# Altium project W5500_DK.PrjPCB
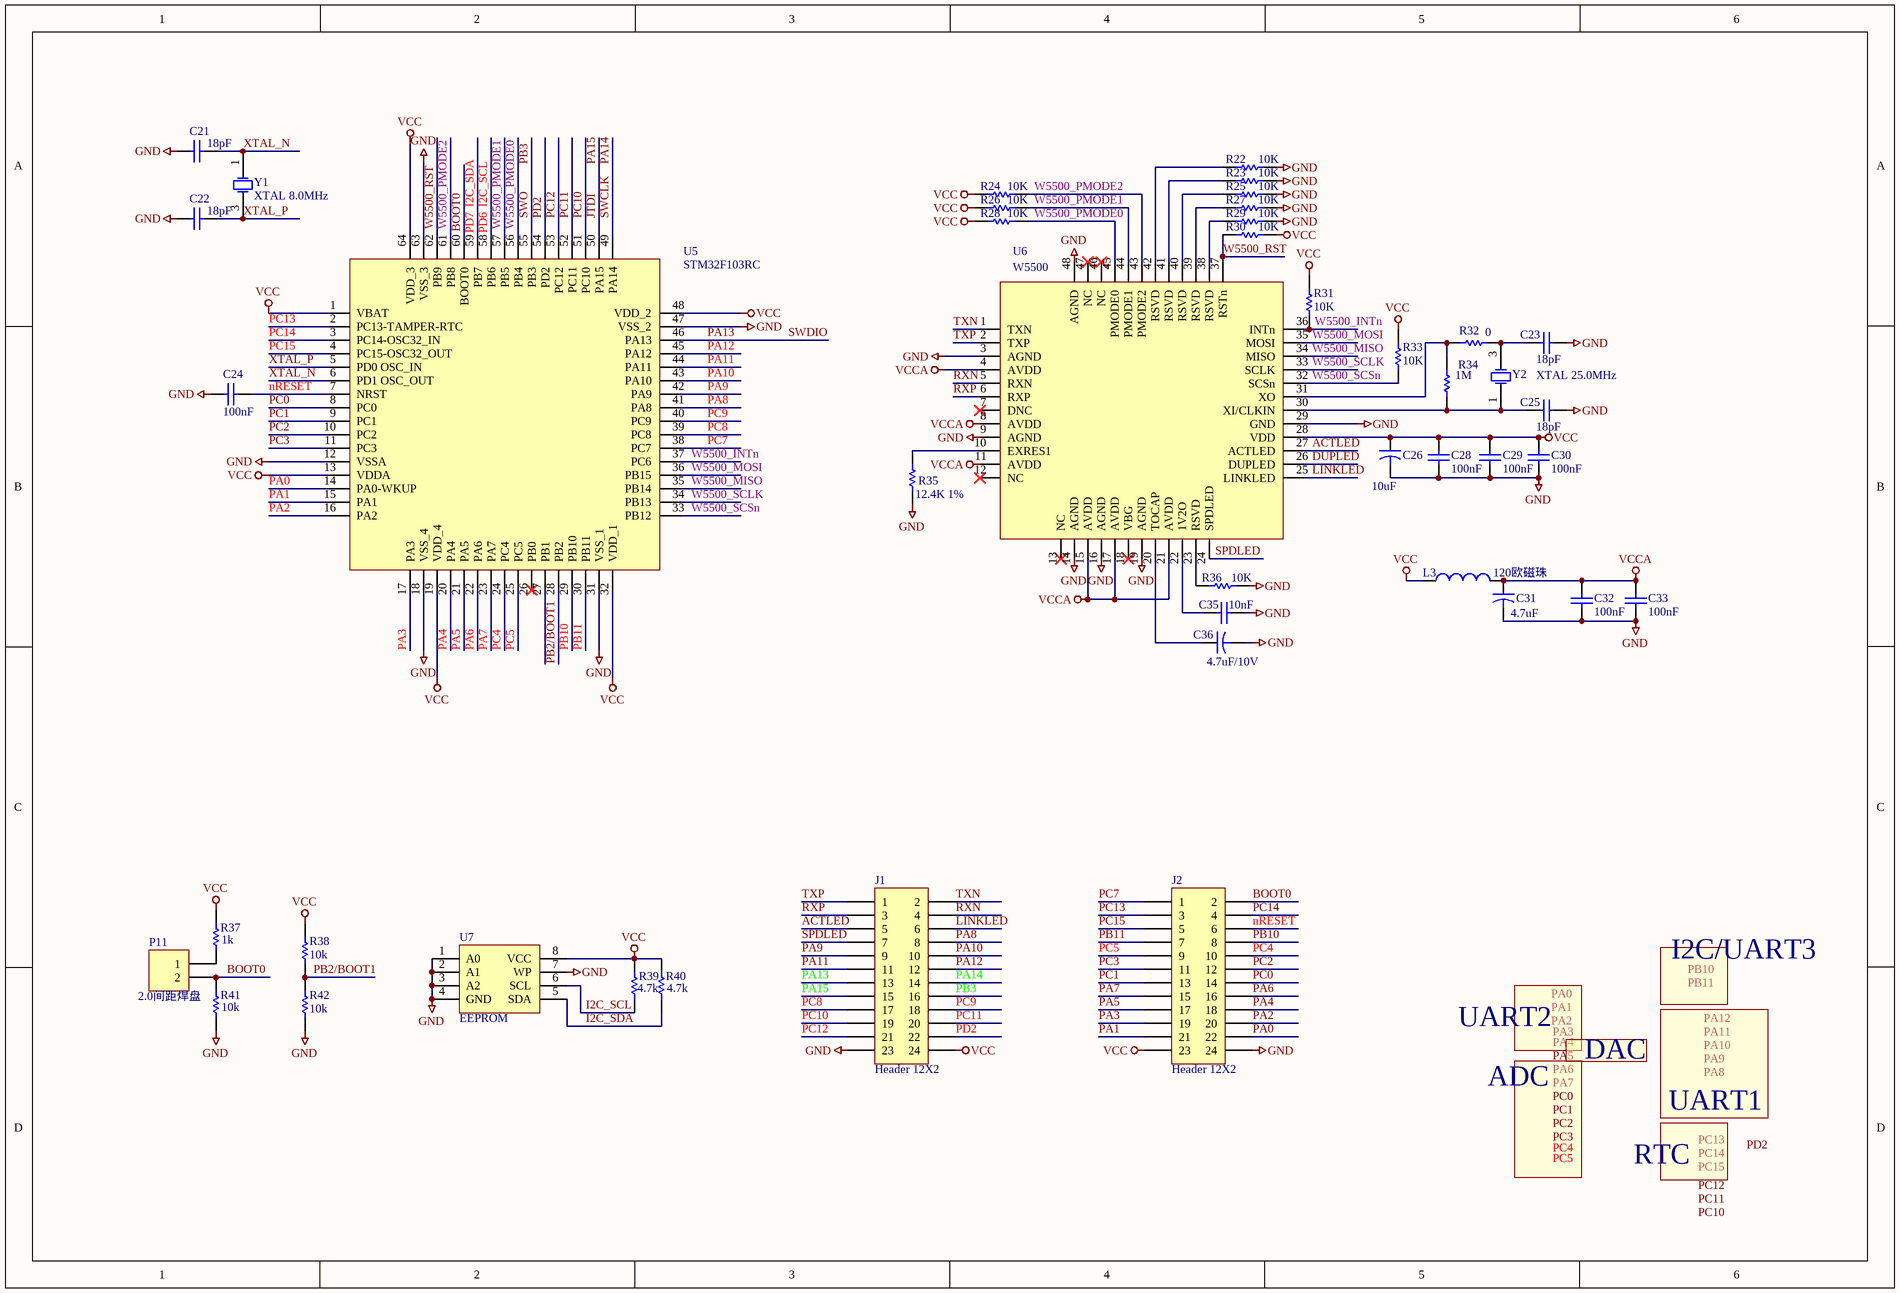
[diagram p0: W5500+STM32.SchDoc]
1 sheet, 44 parts. Net scope: global (net labels, ports and power ports of the same name join across sheets).
Board file: W5500_MODULE.PcbDoc

## Sheet W5500+STM32.SchDoc
size 355 x 241 mm

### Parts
C21  value 18pF  [CR0603]  (hidden comment: Cap)
C22  value 18pF  [CR0603]  (hidden comment: Cap)
C23  value 18pF  [CR0603]  (hidden comment: Cap)
C24  value 100nF  [CR0603]  (hidden comment: Cap)
C25  value 18pF  [CR0603]  (hidden comment: Cap)
C26  value 10uF  [CR0805]  (hidden comment: Cap2)
C28  value 100nF  [CR0603]  (hidden comment: Cap)
C29  value 100nF  [CR0603]  (hidden comment: Cap)
C30  value 100nF  [CR0603]  (hidden comment: Cap)
C31  value 4.7uF  [CR0805]  (hidden comment: Cap2)
C32  value 100nF  [CR0603]  (hidden comment: Cap)
C33  value 100nF  [CR0603]  (hidden comment: Cap)
C35  value 10nF  [CR0603]  (hidden comment: Cap)
C36  value 4.7uF/10V  [CR0805]  (hidden comment: Cap2)
J1  Header 12X2  [HDR2X12]
J2  Header 12X2  [HDR2X12]
L3  value 120欧磁珠  [cr0603]  (hidden comment: Inductor)
P11  2.0间距焊盘  [HDR1X2]
R22  value 10K  [CR0603]  (hidden comment: Res1)
R23  value 10K  [CR0603]  (hidden comment: Res1)
R24  value 10K  [CR0603]  (hidden comment: Res1)
R25  value 10K  [CR0603]  (hidden comment: Res1)
R26  value 10K  [CR0603]  (hidden comment: Res1)
R27  value 10K  [CR0603]  (hidden comment: Res1)
R28  value 10K  [CR0603]  (hidden comment: Res1)
R29  value 10K  [CR0603]  (hidden comment: Res1)
R30  value 10K  [CR0603]  (hidden comment: Res1)
R31  value 10K  [CR0603]  (hidden comment: Res1)
R32  value 0  [CR0603]  (hidden comment: Res1)
R33  value 10K  [CR0603]  (hidden comment: Res1)
R34  value 1M  [CR0603]  (hidden comment: Res1)
R35  value 12.4K 1%  [CR0603]  (hidden comment: Res1)
R36  value 10K  [CR0603]  (hidden comment: Res1)
R37  value 1k  [CR0603]  (hidden comment: Res1)
R38  value 10k  [CR0603]  (hidden comment: Res1)
R39  value 4.7k  [CR0603]  (hidden comment: Res1)
R40  value 4.7k  [CR0603]  (hidden comment: Res1)
R41  value 10k  [CR0603]  (hidden comment: Res1)
R42  value 10k  [CR0603]  (hidden comment: Res1)
U5  STM32F103RC  [LQFP64_M]
U6  W5500  [TQFP48_N]
U7  EEPROM  [8 pin SOIC_M]
Y1  XTAL 8.0MHz  [4pin晶振（FA238）]
Y2  XTAL 25.0MHz  [4pin晶振（FA238）]

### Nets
GND: C21.2 C22.2 C23.2 C24.1 C25.2 C26.2 C28.1 C29.1 C30.1 C31.2 C32.1 C33.1 C35.1 C36.2 J1.23 J2.24 R22.2 R23.2 R25.2 R27.2 R29.2 R35.2 R36.2 R41.2 R42.2 U5.12(VSSA) U5.18(VSS_4) U5.31(VSS_1) U5.47(VSS_2) U5.63(VSS_3) U6.3(AGND) U6.9(AGND) U6.14(AGND) U6.16(AGND) U6.19(AGND) U6.29(GND) U6.48(AGND) U7.1(A0) U7.2(A1) U7.3(A2) U7.4(GND) U7.7(WP)
VCC: C26.1 C28.2 C29.2 C30.2 J1.24 J2.23 L3.1 R24.2 R26.2 R28.2 R30.2 R31.1 R33.1 R37.1 R38.1 R39.1 R40.1 U5.1(VBAT) U5.13(VDDA) U5.19(VDD_4) U5.32(VDD_1) U5.48(VDD_2) U5.64(VDD_3) U6.28(VDD) U7.8(VCC)
VCCA: C31.1 C32.2 C33.2 L3.2 U6.4(AVDD) U6.8(AVDD) U6.11(AVDD) U6.15(AVDD) U6.17(AVDD) U6.21(AVDD)
ACTLED: J1.5 U6.27(ACTLED)
BOOT0: J2.2 P11.2 R41.1 U5.60(BOOT0)
DUPLED: U6.26(DUPLED)
I2C_SCL: R39.2 U5.58(PB6) U7.6(SCL)  [also labelled PD6]
I2C_SDA: R40.2 U5.59(PB7) U7.5(SDA)  [also labelled PD7]
JTDI: J1.15 U5.50(PA15)  [also labelled PA15]
LINKLED: J1.6 U6.25(LINKLED)
nRESET: C24.2 J2.6 U5.7(NRST)
PA0: J2.22 U5.14(PA0-WKUP)
PA1: J2.21 U5.15(PA1)
PA2: J2.20 U5.16(PA2)
PA3: J2.19 U5.17(PA3)
PA4: J2.18 U5.20(PA4)
PA5: J2.17 U5.21(PA5)
PA6: J2.16 U5.22(PA6)
PA7: J2.15 U5.23(PA7)
PA8: J1.8 U5.41(PA8)
PA9: J1.9 U5.42(PA9)
PA10: J1.10 U5.43(PA10)
PA11: J1.11 U5.44(PA11)
PA12: J1.12 U5.45(PA12)
PA13: J1.13 U5.46(PA13)  [also labelled SWDIO]
PA14: J1.14 U5.49(PA14)  [also labelled SWCLK]
PB2/BOOT1: R38.2 R42.1 U5.28(PB2)
PB3: J1.16 U5.55(PB3)  [also labelled SWO]
PB10: J2.8 U5.29(PB10)
PB11: J2.7 U5.30(PB11)
PC0: J2.14 U5.8(PC0)
PC1: J2.13 U5.9(PC1)
PC2: J2.12 U5.10(PC2)
PC3: J2.11 U5.11(PC3)
PC4: J2.10 U5.24(PC4)
PC5: J2.9 U5.25(PC5)
PC7: J2.1 U5.38(PC7)
PC8: J1.17 U5.39(PC8)
PC9: J1.18 U5.40(PC9)
PC10: J1.19 U5.51(PC10)
PC11: J1.20 U5.52(PC11)
PC12: J1.21 U5.53(PC12)
PC13: J2.3 U5.2(PC13-TAMPER-RTC)
PC14: J2.4 U5.3(PC14-OSC32_IN)
PC15: J2.5 U5.4(PC15-OSC32_OUT)
PD2: J1.22 U5.54(PD2)
RXN: J1.4 U6.5(RXN)
RXP: J1.3 U6.6(RXP)
SPDLED: J1.7 U6.24(SPDLED)
TXN: J1.2 U6.1(TXN)
TXP: J1.1 U6.2(TXP)
W5500_INTn: R31.2 U5.37(PC6) U6.36(INTn)
W5500_MISO: U5.35(PB14) U6.34(MISO)
W5500_MOSI: U5.36(PB15) U6.35(MOSI)
W5500_PMODE0: R28.1 U5.56(PB4) U6.45(PMODE0)
W5500_PMODE1: R26.1 U5.57(PB5) U6.44(PMODE1)
W5500_PMODE2: R24.1 U5.61(PB8) U6.43(PMODE2)
W5500_RST: R30.1 U5.62(PB9) U6.37(RSTn)
W5500_SCLK: U5.34(PB13) U6.33(SCLK)
W5500_SCSn: R33.2 U5.33(PB12) U6.32(SCSn)
XTAL_N: C21.1 U5.6(PD1_OSC_OUT) Y1.1(OSC1)
XTAL_P: C22.1 U5.5(PD0_OSC_IN) Y1.3(OSC2)
NetC23_1: C23.1 R32.1 Y2.3(OSC2)
NetC25_1: C25.1 R34.1 U6.30(XI/CLKIN) Y2.1(OSC1)
NetC35_2: C35.2 U6.22(1V2O)
NetC36_1: C36.1 U6.20(TOCAP)
NetP11_1: P11.1 R37.2
NetR22_1: R22.1 U6.42(RSVD)
NetR23_1: R23.1 U6.41(RSVD)
NetR25_1: R25.1 U6.40(RSVD)
NetR27_1: R27.1 U6.39(RSVD)
NetR29_1: R29.1 U6.38(RSVD)
NetR32_2: R32.2 R34.2 U6.31(XO)
NetR35_1: R35.1 U6.10(EXRES1)
NetR36_1: R36.1 U6.23(RSVD)

Not connected (* = marked no-connect by the designer): U5 26(PB0)* 27(PB1); U6 7(DNC)* 12(NC)* 13(NC)* 18(VBG)* 46(NC)* 47(NC)*

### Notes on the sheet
- I2C/UART3
- UART2
- ADC
- DAC
- UART1
- RTC
- Labels drawn without touching a wire or pin: PA0, PA1, PA2, PA3, PA4, PA5, PA6, PA7, PA8, PA9, PA10, PA11, PA12, PB10, PB11, PC0, PC1, PC2, PC3, PC4, PC5, PC10, PC11, PC12, PC13, PC14, PC15, PD2

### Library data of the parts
C21-C25 C28-C30 C32 C33 C35 = Cap: Capacitor
C26 C31 C36 = Cap2: Capacitor
J1 J2 = Header 12X2: Header, 12-Pin, Dual row
L3 = Inductor: Code_IEC: 1005
P11 = Header 2: Header, 2-Pin
R22-R42 = Res1: Resistor
U7 = 24XX01
Y1 Y2 = XTAL: Crystal Oscillator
